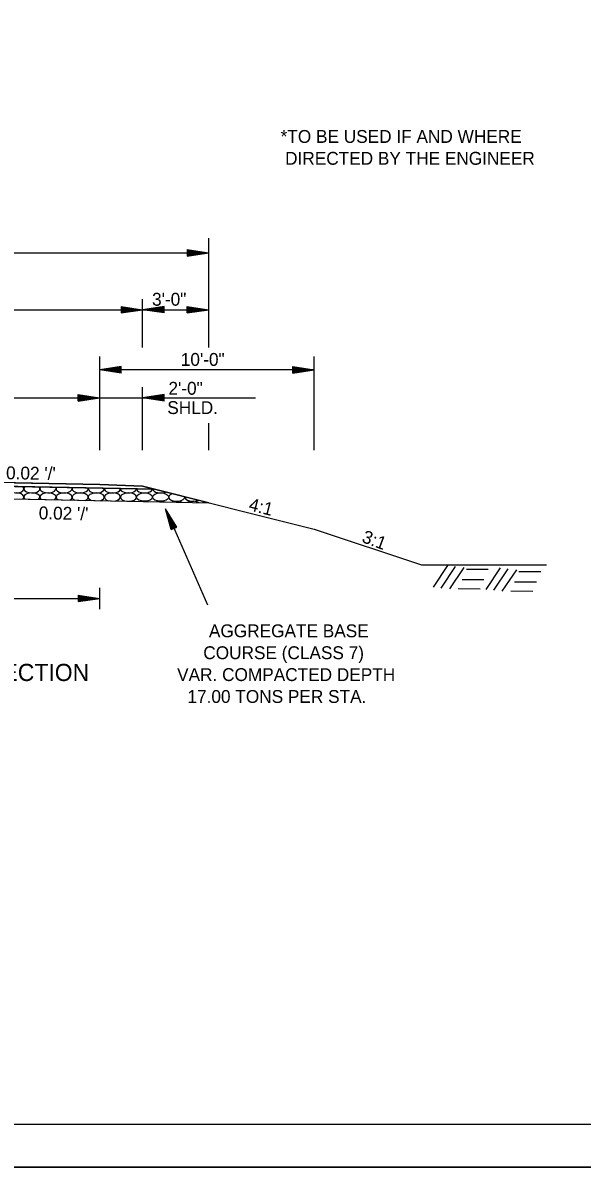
# Model space of a CAD drawing. Extents: x 1371763 to 1372860, y 385599 to 385872.
# Drawn here: x 1372775.9 to 1372801.9, y 385598.6 to 385651.9 of the extents above; entities that cross this region are included whole.
import ezdxf

# ---------------------------------------------------------------- set-up
doc = ezdxf.new("R2010")
doc.units = 0
for name, color, linetype in [('R_Border', 7, 'Continuous'), ('R_Draft', 7, 'Continuous'), ('R_Fin Surface', 7, 'Continuous'), ('R_No Plot', 7, 'Continuous')]:
    doc.layers.add(name, color=color, linetype=linetype)

msp = doc.modelspace()

# ---------------------------------------------------------------- linework, layer by layer
at = {"layer": 'R_Border'}
msp.add_line((1372857.298, 385600.577), (1372699.208, 385600.577), dxfattribs=at)
at = {"layer": 'R_Draft'}
for p, q in [((1372784.541, 385636.792), (1372784.541, 385641.892)), ((1372783.541, 385641.351), (1372784.541, 385641.201)), ((1372783.541, 385641.351), (1372783.541, 385641.051)), ((1372783.541, 385641.326), (1372784.374, 385641.201)), ((1372752.376, 385641.201), (1372784.541, 385641.201)), ((1372783.541, 385641.301), (1372784.202, 385641.201)), ((1372783.541, 385641.276), (1372784.035, 385641.201)), ((1372783.541, 385641.25), (1372783.866, 385641.201)), ((1372783.541, 385641.225), (1372783.699, 385641.201)), ((1372783.541, 385641.051), (1372784.541, 385641.201)), ((1372783.541, 385641.152), (1372783.866, 385641.201)), ((1372783.541, 385641.102), (1372784.202, 385641.201)), ((1372783.541, 385641.076), (1372784.374, 385641.201)), ((1372783.541, 385641.127), (1372784.035, 385641.201)), ((1372783.541, 385641.178), (1372783.699, 385641.201)), ((1372780.46, 385638.699), (1372781.46, 385638.549)), ((1372780.46, 385638.699), (1372780.46, 385638.399)), ((1372780.46, 385638.674), (1372781.293, 385638.549)), ((1372780.46, 385638.649), (1372781.121, 385638.549)), ((1372781.46, 385636.792), (1372781.46, 385639.037)), ((1372782.46, 385638.699), (1372781.46, 385638.549)), ((1372782.46, 385638.674), (1372781.627, 385638.549)), ((1372782.46, 385638.649), (1372781.799, 385638.549)), ((1372782.46, 385638.399), (1372782.46, 385638.699)), ((1372783.541, 385638.699), (1372784.541, 385638.549)), ((1372783.541, 385638.399), (1372783.541, 385638.699)), ((1372783.541, 385638.674), (1372784.374, 385638.549)), ((1372783.541, 385638.649), (1372784.202, 385638.549)), ((1372755.463, 385638.549), (1372781.46, 385638.549)), ((1372780.46, 385638.624), (1372780.955, 385638.549)), ((1372780.46, 385638.598), (1372780.785, 385638.549)), ((1372780.46, 385638.573), (1372780.618, 385638.549)), ((1372780.46, 385638.399), (1372781.46, 385638.549)), ((1372780.46, 385638.5), (1372780.785, 385638.549)), ((1372780.46, 385638.45), (1372781.121, 385638.549)), ((1372780.46, 385638.424), (1372781.293, 385638.549)), ((1372780.46, 385638.475), (1372780.955, 385638.549)), ((1372780.46, 385638.526), (1372780.618, 385638.549)), ((1372782.46, 385638.399), (1372781.46, 385638.549)), ((1372781.46, 385638.549), (1372784.541, 385638.549)), ((1372782.46, 385638.424), (1372781.627, 385638.549)), ((1372782.46, 385638.45), (1372781.799, 385638.549)), ((1372782.46, 385638.624), (1372781.966, 385638.549)), ((1372782.46, 385638.475), (1372781.966, 385638.549)), ((1372782.46, 385638.598), (1372782.135, 385638.549)), ((1372782.46, 385638.501), (1372782.135, 385638.549)), ((1372782.46, 385638.573), (1372782.302, 385638.549)), ((1372782.46, 385638.526), (1372782.302, 385638.549)), ((1372783.541, 385638.624), (1372784.035, 385638.549)), ((1372783.541, 385638.598), (1372783.866, 385638.549)), ((1372783.541, 385638.573), (1372783.699, 385638.549)), ((1372783.541, 385638.399), (1372784.541, 385638.549)), ((1372783.541, 385638.501), (1372783.866, 385638.549)), ((1372783.541, 385638.45), (1372784.202, 385638.549)), ((1372783.541, 385638.424), (1372784.374, 385638.549)), ((1372783.541, 385638.475), (1372784.035, 385638.549)), ((1372783.541, 385638.526), (1372783.699, 385638.549)), ((1372779.462, 385632.006), (1372779.462, 385636.371)), ((1372789.462, 385632.006), (1372789.462, 385636.371)), ((1372780.462, 385635.896), (1372779.462, 385635.746)), ((1372789.462, 385635.746), (1372779.462, 385635.746)), ((1372780.462, 385635.596), (1372779.462, 385635.746)), ((1372780.462, 385635.871), (1372779.629, 385635.746)), ((1372780.462, 385635.621), (1372779.629, 385635.746)), ((1372780.462, 385635.846), (1372779.801, 385635.746)), ((1372780.462, 385635.647), (1372779.801, 385635.746)), ((1372780.462, 385635.821), (1372779.967, 385635.746)), ((1372780.462, 385635.672), (1372779.967, 385635.746)), ((1372780.462, 385635.795), (1372780.137, 385635.746)), ((1372780.462, 385635.698), (1372780.137, 385635.746)), ((1372780.462, 385635.77), (1372780.304, 385635.746)), ((1372780.462, 385635.723), (1372780.304, 385635.746)), ((1372780.462, 385635.596), (1372780.462, 385635.896)), ((1372788.462, 385635.896), (1372789.462, 385635.746)), ((1372788.462, 385635.596), (1372788.462, 385635.896)), ((1372788.462, 385635.871), (1372789.295, 385635.746)), ((1372788.462, 385635.846), (1372789.123, 385635.746)), ((1372788.462, 385635.821), (1372788.956, 385635.746)), ((1372788.462, 385635.795), (1372788.787, 385635.746)), ((1372788.462, 385635.77), (1372788.62, 385635.746)), ((1372788.462, 385635.596), (1372789.462, 385635.746)), ((1372788.462, 385635.698), (1372788.787, 385635.746)), ((1372788.462, 385635.647), (1372789.123, 385635.746)), ((1372788.462, 385635.621), (1372789.295, 385635.746)), ((1372788.462, 385635.672), (1372788.956, 385635.746)), ((1372788.462, 385635.723), (1372788.62, 385635.746)), ((1372781.46, 385632.006), (1372781.46, 385634.933)), ((1372768.458, 385634.445), (1372786.722, 385634.445)), ((1372778.458, 385634.595), (1372779.458, 385634.445)), ((1372778.458, 385634.295), (1372778.458, 385634.595)), ((1372778.458, 385634.57), (1372779.291, 385634.445)), ((1372778.458, 385634.544), (1372779.119, 385634.445)), ((1372778.458, 385634.519), (1372778.953, 385634.445)), ((1372778.458, 385634.494), (1372778.783, 385634.445)), ((1372778.458, 385634.468), (1372778.616, 385634.445)), ((1372778.458, 385634.295), (1372779.458, 385634.445)), ((1372778.458, 385634.396), (1372778.783, 385634.445)), ((1372778.458, 385634.345), (1372779.119, 385634.445)), ((1372778.458, 385634.32), (1372779.291, 385634.445)), ((1372778.458, 385634.37), (1372778.953, 385634.445)), ((1372778.458, 385634.421), (1372778.616, 385634.445)), ((1372782.46, 385634.595), (1372781.46, 385634.445)), ((1372782.46, 385634.295), (1372781.46, 385634.445)), ((1372782.46, 385634.57), (1372781.627, 385634.445)), ((1372782.46, 385634.32), (1372781.627, 385634.445)), ((1372782.46, 385634.544), (1372781.799, 385634.445)), ((1372782.46, 385634.345), (1372781.799, 385634.445)), ((1372782.46, 385634.519), (1372781.966, 385634.445)), ((1372782.46, 385634.37), (1372781.966, 385634.445)), ((1372782.46, 385634.494), (1372782.135, 385634.445)), ((1372782.46, 385634.396), (1372782.135, 385634.445)), ((1372782.46, 385634.468), (1372782.302, 385634.445)), ((1372782.46, 385634.421), (1372782.302, 385634.445)), ((1372782.46, 385634.295), (1372782.46, 385634.595)), ((1372784.541, 385632.006), (1372784.541, 385633.256)), ((1372768.462, 385630.618), (1372779.462, 385630.398)), ((1372768.462, 385630.451), (1372782.011, 385630.18)), ((1372779.462, 385630.398), (1372781.46, 385630.318)), ((1372781.46, 385630.318), (1372789.46, 385628.318)), ((1372768.462, 385629.868), (1372784.547, 385629.546)), ((1372782.523, 385629.274), (1372784.491, 385624.792)), ((1372782.787, 385628.298), (1372782.523, 385629.274)), ((1372783.062, 385628.419), (1372782.523, 385629.274)), ((1372782.81, 385628.308), (1372782.59, 385629.121)), ((1372783.039, 385628.409), (1372782.59, 385629.121)), ((1372783.016, 385628.398), (1372782.659, 385628.964)), ((1372782.834, 385628.318), (1372782.659, 385628.964)), ((1372782.857, 385628.329), (1372782.726, 385628.811)), ((1372782.993, 385628.388), (1372782.726, 385628.811)), ((1372782.97, 385628.378), (1372782.794, 385628.656)), ((1372782.88, 385628.339), (1372782.794, 385628.656)), ((1372782.787, 385628.298), (1372783.062, 385628.419)), ((1372782.946, 385628.368), (1372782.861, 385628.503)), ((1372782.903, 385628.349), (1372782.861, 385628.503)), ((1372789.46, 385628.318), (1372794.46, 385626.651)), ((1372795.013, 385625.62), (1372795.689, 385626.622)), ((1372795.372, 385625.578), (1372796.048, 385626.58)), ((1372795.773, 385625.537), (1372796.449, 385626.538)), ((1372796.549, 385626.463), (1372797.566, 385626.455)), ((1372797.466, 385625.512), (1372798.142, 385626.513)), ((1372797.825, 385625.47), (1372798.501, 385626.471)), ((1372798.226, 385625.428), (1372798.901, 385626.43)), ((1372796.348, 385625.979), (1372797.366, 385625.971)), ((1372798.801, 385625.87), (1372799.819, 385625.862)), ((1372799.001, 385626.355), (1372800.019, 385626.346)), ((1372779.462, 385624.592), (1372779.462, 385625.592)), ((1372796.173, 385625.553), (1372797.191, 385625.545)), ((1372798.626, 385625.445), (1372799.644, 385625.436)), ((1372757.462, 385625.092), (1372779.462, 385625.092)), ((1372778.462, 385625.242), (1372779.462, 385625.092)), ((1372778.462, 385625.242), (1372778.462, 385624.942)), ((1372778.462, 385625.217), (1372779.295, 385625.092)), ((1372778.462, 385625.191), (1372779.123, 385625.092)), ((1372778.462, 385625.166), (1372778.956, 385625.092)), ((1372778.462, 385625.14), (1372778.787, 385625.092)), ((1372778.462, 385625.115), (1372778.62, 385625.092)), ((1372778.462, 385624.942), (1372779.462, 385625.092)), ((1372778.462, 385625.043), (1372778.787, 385625.092)), ((1372778.462, 385624.992), (1372779.123, 385625.092)), ((1372778.462, 385624.967), (1372779.295, 385625.092)), ((1372778.462, 385625.017), (1372778.956, 385625.092)), ((1372778.462, 385625.068), (1372778.62, 385625.092))]:
    msp.add_line(p, q, dxfattribs=at)
for points in [[(1372754.912, 385630.18), (1372752.376, 385629.546), (1372768.462, 385629.868), (1372784.547, 385629.546), (1372782.011, 385630.18), (1372768.462, 385630.451)], [(1372754.912, 385630.18), (1372755.463, 385630.318), (1372757.462, 385630.398), (1372768.462, 385630.618), (1372779.462, 385630.398), (1372781.46, 385630.318), (1372782.011, 385630.18), (1372768.462, 385630.451)]]:
    msp.add_lwpolyline(points, close=True, dxfattribs=at)
msp.add_lwpolyline([(1372768.462, 385630.451), (1372782.011, 385630.18), (1372781.46, 385630.318), (1372779.462, 385630.398), (1372768.462, 385630.618)], dxfattribs=at)
for centre, start_param, end_param in [((1372775.55, 385630.204), 2.527568, 6.820012), ((1372776.3, 385630.204), 2.617084, 6.730496), ((1372777.051, 385630.204), 2.702543, 6.645037), ((1372777.801, 385630.204), 2.785007, 6.562573), ((1372778.551, 385630.204), 2.865286, 6.482294), ((1372779.301, 385630.204), 2.944028, 6.403551), ((1372780.052, 385630.204), 3.021787, 6.325793), ((1372780.802, 385630.204), 3.099055, 6.248524), ((1372781.552, 385630.204), 3.1763, 6.17128), ((1372782.302, 385630.204), 3.253986, 5.370938), ((1372775.55, 385629.815), 5.769249, 9.861516), ((1372776.3, 385629.815), 5.680295, 9.95047), ((1372777.051, 385629.815), 5.586004, 10.044761), ((1372777.801, 385629.815), 5.484236, 10.146529), ((1372778.551, 385629.815), 5.37144, 10.259325), ((1372779.301, 385629.815), 5.240758, 10.390007), ((1372780.052, 385629.815), 5.074684, 10.556081), ((1372780.802, 385629.815), 4.738743, 10.892022), ((1372781.552, 385629.426), 1.138351, 1.926043), ((1372782.302, 385629.426), 0.970328, 2.094066), ((1372783.053, 385629.815), 2.184954, 6.340353), ((1372783.053, 385629.426), 0.838804, 2.22559), ((1372783.803, 385629.815), 3.085963, 5.439345), ((1372783.803, 385629.426), 0.725522, 2.338872), ((1372784.553, 385629.426), 2.112259, 2.440958)]:
    msp.add_ellipse(centre, major_axis=(0.375, 0), ratio=0.517889, start_param=start_param, end_param=end_param, dxfattribs=at)
for centre in [(1372781.552, 385629.815), (1372782.302, 385629.815)]:
    msp.add_ellipse(centre, major_axis=(0.375, 0), ratio=0.517889, dxfattribs=at)
at = {"layer": 'R_Fin Surface'}
msp.add_line((1372794.46, 385626.651), (1372800.278, 385626.651), dxfattribs=at)
at = {"layer": 'R_No Plot'}
msp.add_line((1372693.007, 385598.587), (1372859.674, 385598.587), dxfattribs=at)
for points in [[(1372693.004, 385705.254), (1372859.674, 385705.254), (1372859.674, 385598.585), (1372693.004, 385598.585)], [(1372816.168, 385703.307), (1372825.978, 385703.307), (1372825.978, 385698.367), (1372834.034, 385698.367), (1372845.634, 385698.367), (1372845.634, 385682.032), (1372857.238, 385682.032), (1372857.298, 385600.577), (1372699.208, 385600.577), (1372699.208, 385703.307)]]:
    msp.add_lwpolyline(points, close=True, dxfattribs=at)

# ---------------------------------------------------------------- texts
at = {"layer": 'R_Draft'}
for s, rotation, p in [('*TO BE USED IF AND WHERE ', 360, (1372787.894, 385646.326)), ('DIRECTED BY THE ENGINEER', 360, (1372788.104, 385645.306)), ('3\'-0"', 360, (1372781.902, 385638.737)), ('10\'-0"', 0, (1372783.241, 385635.933)), ('2\'-0"', 360, (1372782.666, 385634.587)), ('SHLD.', 360, (1372782.612, 385633.687)), ("0.02 '/'", 359.0147, (1372775.094, 385630.65)), ('4:1', 345.9638, (1372786.373, 385629.207)), ("0.02 '/'", 359.0147, (1372776.617, 385628.782)), ('3:1', 339.4451, (1372791.638, 385627.733)), ('AGGREGATE BASE ', 360, (1372784.553, 385623.282)), ('COURSE (CLASS 7)', 360, (1372784.289, 385622.262)), ('VAR. COMPACTED DEPTH', 360, (1372783.07, 385621.242)), ('17.00 TONS PER STA.', 360, (1372783.552, 385620.222))]:
    msp.add_text(s, height=0.6, rotation=rotation, dxfattribs=at).set_placement(p)
msp.add_text('E. PLENTYWOOD RD. - FULL DEPTH SECTION', height=0.8, dxfattribs=at).set_placement((1372755.375, 385621.243))

doc.saveas('drawing.dxf')
